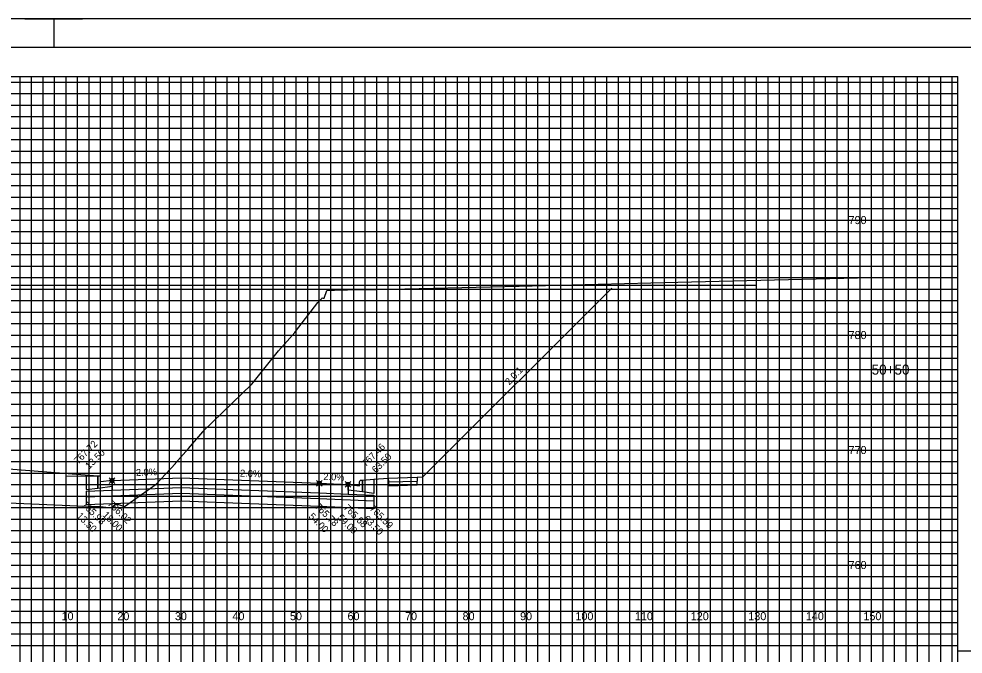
# Model space of a CAD drawing. Extents: x 578243 to 601557, y 174899 to 175559.
# Drawn here: x 600701.6 to 600865.7, y 175008.3 to 175118.8 of the extents above; entities that cross this region are included whole.
import ezdxf

# ---------------------------------------------------------------- set-up
doc = ezdxf.new("R2010")
doc.units = 0
for name, color, linetype in [('E_PROF_Grid', 7, 'Continuous'), ('E_PROF_GridMin', 7, 'Continuous'), ('P_CRDR_Label', 7, 'Continuous'), ('P_CRDR_Link', 7, 'Continuous'), ('P_E_XS_Ground', 7, 'Continuous'), ('P_RW_SlopeIntercepts', 7, 'Continuous'), ('P_XS_Text', 7, 'Continuous'), ('PLT_Sheet_Border', 7, 'Continuous'), ('PLT_Sheet_Info', 7, 'Continuous')]:
    doc.layers.add(name, color=color, linetype=linetype)

msp = doc.modelspace()

# ---------------------------------------------------------------- linework, layer by layer
at = {"layer": 'E_PROF_Grid'}
for p, q in [((600709.84, 174913.8), (600709.84, 175108.8)), ((600719.84, 174913.8), (600719.84, 175108.8)), ((600729.84, 174913.8), (600729.84, 175108.8)), ((600739.84, 174913.8), (600739.84, 175108.8)), ((600749.84, 174913.8), (600749.84, 175108.8)), ((600759.84, 174913.8), (600759.84, 175108.8)), ((600769.84, 174913.8), (600769.84, 175108.8)), ((600779.84, 174913.8), (600779.84, 175108.8)), ((600789.84, 174913.8), (600789.84, 175108.8)), ((600799.84, 174913.8), (600799.84, 175108.8)), ((600809.84, 174913.8), (600809.84, 175108.8)), ((600819.84, 174913.8), (600819.84, 175108.8)), ((600829.84, 174913.8), (600829.84, 175108.8)), ((600839.84, 174913.8), (600839.84, 175108.8)), ((600849.84, 174913.8), (600849.84, 175108.8)), ((600859.84, 174913.8), (600859.84, 175108.8)), ((600549.84, 175103.8), (600864.84, 175103.8)), ((600549.84, 175093.8), (600864.84, 175093.8)), ((600549.84, 175083.8), (600864.84, 175083.8)), ((600549.84, 175073.8), (600864.84, 175073.8)), ((600549.84, 175063.8), (600864.84, 175063.8)), ((600549.84, 175053.8), (600864.84, 175053.8)), ((600549.84, 175043.8), (600864.84, 175043.8)), ((600549.84, 175033.8), (600864.84, 175033.8)), ((600549.84, 175023.8), (600864.84, 175023.8)), ((600549.84, 175013.8), (600864.84, 175013.8))]:
    msp.add_line(p, q, dxfattribs=at)
at = {"layer": 'E_PROF_GridMin'}
for p, q in [((600701.84, 174913.8), (600701.84, 175108.8)), ((600703.84, 174913.8), (600703.84, 175108.8)), ((600705.84, 174913.8), (600705.84, 175108.8)), ((600707.84, 174913.8), (600707.84, 175108.8)), ((600711.84, 174913.8), (600711.84, 175108.8)), ((600713.84, 174913.8), (600713.84, 175108.8)), ((600715.84, 174913.8), (600715.84, 175108.8)), ((600717.84, 174913.8), (600717.84, 175108.8)), ((600721.84, 174913.8), (600721.84, 175108.8)), ((600723.84, 174913.8), (600723.84, 175108.8)), ((600725.84, 174913.8), (600725.84, 175108.8)), ((600727.84, 174913.8), (600727.84, 175108.8)), ((600731.84, 174913.8), (600731.84, 175108.8)), ((600733.84, 174913.8), (600733.84, 175108.8)), ((600735.84, 174913.8), (600735.84, 175108.8)), ((600737.84, 174913.8), (600737.84, 175108.8)), ((600741.84, 174913.8), (600741.84, 175108.8)), ((600743.84, 174913.8), (600743.84, 175108.8)), ((600745.84, 174913.8), (600745.84, 175108.8)), ((600747.84, 174913.8), (600747.84, 175108.8)), ((600751.84, 174913.8), (600751.84, 175108.8)), ((600753.84, 174913.8), (600753.84, 175108.8)), ((600755.84, 174913.8), (600755.84, 175108.8)), ((600757.84, 174913.8), (600757.84, 175108.8)), ((600761.84, 174913.8), (600761.84, 175108.8)), ((600763.84, 174913.8), (600763.84, 175108.8)), ((600765.84, 174913.8), (600765.84, 175108.8)), ((600767.84, 174913.8), (600767.84, 175108.8)), ((600771.84, 174913.8), (600771.84, 175108.8)), ((600773.84, 174913.8), (600773.84, 175108.8)), ((600775.84, 174913.8), (600775.84, 175108.8)), ((600777.84, 174913.8), (600777.84, 175108.8)), ((600781.84, 174913.8), (600781.84, 175108.8)), ((600783.84, 174913.8), (600783.84, 175108.8)), ((600785.84, 174913.8), (600785.84, 175108.8)), ((600787.84, 174913.8), (600787.84, 175108.8)), ((600791.84, 174913.8), (600791.84, 175108.8)), ((600793.84, 174913.8), (600793.84, 175108.8)), ((600795.84, 174913.8), (600795.84, 175108.8)), ((600797.84, 174913.8), (600797.84, 175108.8)), ((600801.84, 174913.8), (600801.84, 175108.8)), ((600803.84, 174913.8), (600803.84, 175108.8)), ((600805.84, 174913.8), (600805.84, 175108.8)), ((600807.84, 174913.8), (600807.84, 175108.8)), ((600811.84, 174913.8), (600811.84, 175108.8)), ((600813.84, 174913.8), (600813.84, 175108.8)), ((600815.84, 174913.8), (600815.84, 175108.8)), ((600817.84, 174913.8), (600817.84, 175108.8)), ((600821.84, 174913.8), (600821.84, 175108.8)), ((600823.84, 174913.8), (600823.84, 175108.8)), ((600825.84, 174913.8), (600825.84, 175108.8)), ((600827.84, 174913.8), (600827.84, 175108.8)), ((600831.84, 174913.8), (600831.84, 175108.8)), ((600833.84, 174913.8), (600833.84, 175108.8)), ((600835.84, 174913.8), (600835.84, 175108.8)), ((600837.84, 174913.8), (600837.84, 175108.8)), ((600841.84, 174913.8), (600841.84, 175108.8)), ((600843.84, 174913.8), (600843.84, 175108.8)), ((600845.84, 174913.8), (600845.84, 175108.8)), ((600847.84, 174913.8), (600847.84, 175108.8)), ((600851.84, 174913.8), (600851.84, 175108.8)), ((600853.84, 174913.8), (600853.84, 175108.8)), ((600855.84, 174913.8), (600855.84, 175108.8)), ((600857.84, 174913.8), (600857.84, 175108.8)), ((600861.84, 174913.8), (600861.84, 175108.8)), ((600863.84, 174913.8), (600863.84, 175108.8)), ((600549.84, 175107.8), (600864.84, 175107.8)), ((600549.84, 175105.8), (600864.84, 175105.8)), ((600549.84, 175101.8), (600864.84, 175101.8)), ((600549.84, 175099.8), (600864.84, 175099.8)), ((600549.84, 175097.8), (600864.84, 175097.8)), ((600549.84, 175095.8), (600864.84, 175095.8)), ((600549.84, 175091.8), (600864.84, 175091.8)), ((600549.84, 175089.8), (600864.84, 175089.8)), ((600549.84, 175087.8), (600864.84, 175087.8)), ((600549.84, 175085.8), (600864.84, 175085.8)), ((600549.84, 175081.8), (600864.84, 175081.8)), ((600549.84, 175079.8), (600864.84, 175079.8)), ((600549.84, 175077.8), (600864.84, 175077.8)), ((600549.84, 175075.8), (600864.84, 175075.8)), ((600549.84, 175071.8), (600864.84, 175071.8)), ((600549.84, 175069.8), (600864.84, 175069.8)), ((600549.84, 175067.8), (600864.84, 175067.8)), ((600549.84, 175065.8), (600864.84, 175065.8)), ((600549.84, 175061.8), (600864.84, 175061.8)), ((600549.84, 175059.8), (600864.84, 175059.8)), ((600549.84, 175057.8), (600864.84, 175057.8)), ((600549.84, 175055.8), (600864.84, 175055.8)), ((600549.84, 175051.8), (600864.84, 175051.8)), ((600549.84, 175049.8), (600864.84, 175049.8)), ((600549.84, 175047.8), (600864.84, 175047.8)), ((600549.84, 175045.8), (600864.84, 175045.8)), ((600549.84, 175041.8), (600864.84, 175041.8)), ((600549.84, 175039.8), (600864.84, 175039.8)), ((600549.84, 175037.8), (600864.84, 175037.8)), ((600549.84, 175035.8), (600864.84, 175035.8)), ((600549.84, 175031.8), (600864.84, 175031.8)), ((600549.84, 175029.8), (600864.84, 175029.8)), ((600549.84, 175027.8), (600864.84, 175027.8)), ((600549.84, 175025.8), (600864.84, 175025.8)), ((600549.84, 175021.8), (600864.84, 175021.8)), ((600549.84, 175019.8), (600864.84, 175019.8)), ((600549.84, 175017.8), (600864.84, 175017.8)), ((600549.84, 175015.8), (600864.84, 175015.8)), ((600549.84, 175011.8), (600864.84, 175011.8)), ((600549.84, 175009.8), (600864.84, 175009.8))]:
    msp.add_line(p, q, dxfattribs=at)
at = {"layer": 'P_CRDR_Label'}
for points in [[(600717.35, 175038), (600718.34, 175038.99)], [(600717.35, 175038.99), (600718.34, 175038)], [(600753.35, 175037.52), (600754.34, 175038.51)], [(600753.35, 175038.51), (600754.34, 175037.52)], [(600758.35, 175037.32), (600759.34, 175038.31)], [(600758.35, 175038.31), (600759.34, 175037.32)]]:
    msp.add_lwpolyline(points, dxfattribs=at)
for centre in [(600717.84, 175038.5), (600753.84, 175038.02), (600758.84, 175037.82)]:
    msp.add_circle(centre, 0.35, dxfattribs=at)
at = {"layer": 'P_CRDR_Link'}
msp.add_line((600804.69, 175071.96), (600771.84, 175039.11), dxfattribs=at)
for points in [[(600715.34, 175039.25), (600699.84, 175040.49)], [(600715.34, 175039.25), (600699.84, 175040.49)], [(600713.34, 175039.23), (600709.84, 175039.2)], [(600713.34, 175039.23), (600709.84, 175039.2)], [(600715.34, 175039.25), (600713.34, 175039.23)], [(600713.34, 175039.23), (600713.34, 175036.93)], [(600713.34, 175039.23), (600713.34, 175036.93)], [(600713.34, 175039.23), (600713.34, 175036.93)], [(600715.66, 175039.25), (600715.34, 175039.25)], [(600715.66, 175039.25), (600715.34, 175039.25)], [(600715.34, 175039.25), (600715.34, 175037.18)], [(600715.34, 175037.18), (600715.34, 175039.25)], [(600715.74, 175039.2), (600715.66, 175039.25)], [(600715.74, 175039.2), (600715.66, 175039.25)], [(600715.8, 175039.09), (600715.74, 175039.2)], [(600715.8, 175039.09), (600715.74, 175039.2)], [(600715.83, 175038.93), (600715.8, 175039.09)], [(600715.83, 175038.93), (600715.8, 175039.09)], [(600715.84, 175038.25), (600715.83, 175038.93)], [(600715.84, 175038.25), (600715.83, 175038.93)], [(600717.84, 175038.5), (600715.84, 175038.25)], [(600717.84, 175038.5), (600715.84, 175038.25)], [(600717.84, 175038.5), (600729.84, 175038.98)], [(600717.84, 175037.5), (600717.84, 175038.5)], [(600717.84, 175038.5), (600717.84, 175036.83)], [(600729.84, 175038.98), (600729.84, 175037.31)], [(600729.84, 175038.98), (600753.84, 175038.02)], [(600729.84, 175038.98), (600729.84, 175037.31)], [(600753.84, 175038.02), (600753.84, 175036.35)], [(600753.84, 175038.02), (600758.84, 175037.82)], [(600753.84, 175038.02), (600753.84, 175036.35)], [(600758.84, 175037.82), (600758.84, 175036.15)], [(600758.84, 175037.82), (600760.84, 175037.57)], [(600758.84, 175037.82), (600760.84, 175037.57)], [(600758.84, 175036.82), (600758.84, 175037.82)], [(600760.84, 175037.57), (600760.85, 175038.25)], [(600760.84, 175037.57), (600760.85, 175038.25)], [(600760.85, 175038.25), (600760.88, 175038.41)], [(600760.85, 175038.25), (600760.88, 175038.41)], [(600760.88, 175038.41), (600760.94, 175038.52)], [(600760.88, 175038.41), (600760.94, 175038.52)], [(600760.94, 175038.52), (600761.02, 175038.57)], [(600760.94, 175038.52), (600761.02, 175038.57)], [(600761.02, 175038.57), (600761.34, 175038.57)], [(600761.02, 175038.57), (600761.34, 175038.57)], [(600761.34, 175038.57), (600763.34, 175038.73)], [(600761.34, 175038.57), (600761.34, 175036.5)], [(600761.34, 175036.5), (600761.34, 175038.57)], [(600763.34, 175038.73), (600765.84, 175038.93)], [(600763.34, 175038.73), (600765.84, 175038.93)], [(600763.34, 175038.73), (600763.34, 175036.25)], [(600763.34, 175038.73), (600763.34, 175036.25)], [(600763.34, 175038.73), (600763.34, 175036.25)], [(600765.84, 175038.93), (600770.84, 175039.08)], [(600765.84, 175038.93), (600770.84, 175039.08)], [(600765.84, 175038.93), (600765.85, 175038.26)], [(600765.85, 175038.26), (600770.84, 175038.41)], [(600765.85, 175038.26), (600765.85, 175037.6)], [(600765.85, 175037.6), (600770.83, 175037.75)], [(600770.83, 175037.75), (600770.84, 175038.41)], [(600770.84, 175039.08), (600771.84, 175039.11)], [(600770.84, 175039.08), (600771.84, 175039.11)], [(600770.84, 175039.08), (600770.84, 175038.41)], [(600713.34, 175036.93), (600715.34, 175037.18)], [(600713.34, 175036.65), (600717.84, 175036.83)], [(600713.34, 175036.65), (600713.34, 175035.65)], [(600713.34, 175035.65), (600729.84, 175036.31)], [(600715.34, 175037.18), (600717.84, 175037.5)], [(600715.34, 175037.18), (600717.84, 175037.5)], [(600717.84, 175036.83), (600729.84, 175037.31)], [(600729.84, 175037.31), (600729.84, 175036.31)], [(600729.84, 175037.31), (600753.84, 175036.35)], [(600729.84, 175037.31), (600729.84, 175036.31)], [(600729.84, 175036.31), (600729.84, 175034.98)], [(600729.84, 175036.31), (600753.84, 175035.35)], [(600729.84, 175036.31), (600729.84, 175034.98)], [(600753.84, 175036.35), (600753.84, 175035.35)], [(600753.84, 175036.35), (600758.84, 175036.15)], [(600753.84, 175036.35), (600753.84, 175035.35)], [(600761.34, 175036.5), (600758.84, 175036.82)], [(600761.34, 175036.5), (600758.84, 175036.82)], [(600758.84, 175036.15), (600763.34, 175035.97)], [(600763.34, 175036.25), (600761.34, 175036.5)], [(600763.34, 175035.97), (600763.34, 175034.97)], [(600713.34, 175035.65), (600713.34, 175034.32)], [(600713.34, 175034.32), (600729.84, 175034.98)], [(600729.84, 175034.98), (600753.84, 175034.02)], [(600753.84, 175035.35), (600753.84, 175034.02)], [(600753.84, 175035.35), (600763.34, 175034.97)], [(600753.84, 175035.35), (600753.84, 175034.02)], [(600763.34, 175034.97), (600763.34, 175033.64)], [(600753.84, 175034.02), (600763.34, 175033.64)]]:
    msp.add_lwpolyline(points, dxfattribs=at)
at = {"layer": 'P_E_XS_Ground'}
msp.add_lwpolyline([(600699.84, 175034.6), (600711.84, 175034.12), (600715.78, 175033.97), (600717.78, 175033.72), (600718.36, 175034.38), (600718.78, 175034.38), (600718.78, 175034.38), (600719.99, 175033.98), (600725.49, 175037.88), (600725.5, 175037.89), (600725.5, 175037.89), (600728.86, 175041.48), (600728.87, 175041.49), (600729.73, 175042.49), (600731.11, 175044.08), (600731.12, 175044.09), (600733.6, 175046.97), (600733.62, 175047), (600742.15, 175055.28), (600746.74, 175061.04), (600748.29, 175062.76), (600749.57, 175064.24), (600749.71, 175064.43), (600753.6, 175069.47), (600754.35, 175070.23), (600754.36, 175070.25), (600754.54, 175070.23), (600754.7, 175070.23), (600755.14, 175071.57), (600756.5, 175071.6), (600758.77, 175071.66), (600763.75, 175071.74), (600788.59, 175072.32), (600811.45, 175072.9), (600818.54, 175073.04), (600849.84, 175073.79)], dxfattribs=at)
at = {"layer": 'P_RW_SlopeIntercepts'}
msp.add_line((600593.84, 175072.48), (600829.84, 175072.48), dxfattribs=at)
at = {"layer": 'PLT_Sheet_Border'}
for points in [[(600537.19, 174898.8), (600877.19, 174898.8), (600877.19, 175118.8), (600537.19, 175118.8)], [(600539.59, 174903.8), (600870.59, 174903.8), (600870.59, 175113.8), (600539.59, 175113.8)]]:
    msp.add_lwpolyline(points, close=True, dxfattribs=at)
at = {"layer": 'PLT_Sheet_Info'}
for p, q in [((600702.69, 175118.8), (600712.69, 175118.8)), ((600707.69, 175118.8), (600707.69, 175113.8)), ((600549.84, 175108.8), (600864.84, 175108.8)), ((600864.84, 174908.8), (600864.84, 175108.8)), ((600877.19, 175008.8), (600864.84, 175008.8))]:
    msp.add_line(p, q, dxfattribs=at)

# ---------------------------------------------------------------- texts
at = {"layer": 'P_CRDR_Label'}
for s, rotation, p in [('2.0:1', 46.711, (600786.88, 175055.02)), ('767.72', 45, (600711.93, 175041.27)), ('767.46', 45, (600761.93, 175040.77)), ('13.50', 45, (600713.87, 175040.39)), ('63.50', 45, (600763.69, 175039.71)), ('2.0%', 2.2906, (600722, 175039.28)), ('2.0%', 357.7094, (600740.05, 175039.19)), ('2.0%', 357.7094, (600754.55, 175038.61)), ('765.93', 315, (600712.49, 175034.17)), ('766.02', 315, (600716.99, 175034.35)), ('765.78', 315, (600752.99, 175033.87)), ('765.68', 315, (600757.99, 175033.67)), ('765.59', 315, (600762.49, 175033.49)), ('13.50', 315, (600711.61, 175032.23)), ('18.00', 315, (600716.1, 175032.41)), ('54.00', 315, (600751.9, 175032.14)), ('59.00', 315, (600756.89, 175031.94)), ('63.50', 315, (600761.43, 175031.73))]:
    msp.add_text(s, height=1.2, rotation=rotation, dxfattribs=at).set_placement(p)
at = {"layer": 'P_XS_Text'}
for s, height, p in [('790', 1.4, (600845.84, 175083.1)), ('780', 1.4, (600845.84, 175063.1)), ('50+50', 1.75, (600849.84, 175056.92)), ('770', 1.4, (600845.84, 175043.1)), ('760', 1.4, (600845.84, 175023.1)), ('10', 1.4, (600709.05, 175014.2)), ('20', 1.4, (600718.75, 175014.2)), ('30', 1.4, (600728.75, 175014.2)), ('40', 1.4, (600738.75, 175014.2)), ('50', 1.4, (600748.75, 175014.2)), ('60', 1.4, (600758.75, 175014.2)), ('70', 1.4, (600768.75, 175014.2)), ('80', 1.4, (600778.75, 175014.2)), ('90', 1.4, (600788.74, 175014.2)), ('100', 1.4, (600798.36, 175014.2)), ('110', 1.4, (600808.7, 175014.2)), ('120', 1.4, (600818.41, 175014.2)), ('130', 1.4, (600828.41, 175014.2)), ('140', 1.4, (600838.41, 175014.2)), ('150', 1.4, (600848.41, 175014.2))]:
    msp.add_text(s, height=height, rotation=360, dxfattribs=at).set_placement(p)

doc.saveas('drawing.dxf')
